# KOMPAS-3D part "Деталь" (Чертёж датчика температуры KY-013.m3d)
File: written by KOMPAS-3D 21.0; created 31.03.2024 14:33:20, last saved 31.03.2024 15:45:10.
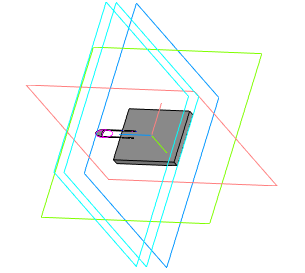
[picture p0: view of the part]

Document properties: Автор: Школа; Полное имя файла: C:\Users\Школа\Desktop\КУБСАТ ПРЕДПРОФФ\Чертёж датчика температуры KY-013.m3d

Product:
- Part/product: Деталь
    Масса: 0.004258

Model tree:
1. Эскиз:1
2. Элемент выдавливания:1
     Расстояние 1 = 2
3. Эскиз:2  (with: Элемент выдавливания:1)
4. Смещенная плоскость:5
     Расстояние = 9
5. Эскиз:3
6. Эскиз:4
7. Эскиз:5  (with: Элемент выдавливания:1)
8. Эскиз:6
9. Контур:1
10. Контур:2
11. Контур:3
12. Контур:4
13. Смещенная плоскость:7
     Расстояние = 3
14. Эскиз:7
15. Элемент по сечениям:1
16. Элемент выдавливания:2
     Расстояние 2 = 10
17. Зеркальный массив:1
18. Экземпляр ( 1 )
19. Экземпляр ( 2 )  (with: Элемент по сечениям:1)
20. Элемент выдавливания:3  (with: Элемент выдавливания:2)
     Расстояние 2 = 5
21. Эскиз:8  (with: Элемент выдавливания:3)
22. Элемент выдавливания:4
     Расстояние 1 = 0.3
23. Элемент выдавливания:5
     Расстояние 2 = 0.1
24. Скругление:3  (with: Элемент выдавливания:4)
     Радиус = 0.1
25. Скругление:4  (with: Элемент выдавливания:5)
     Радиус = 0.1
